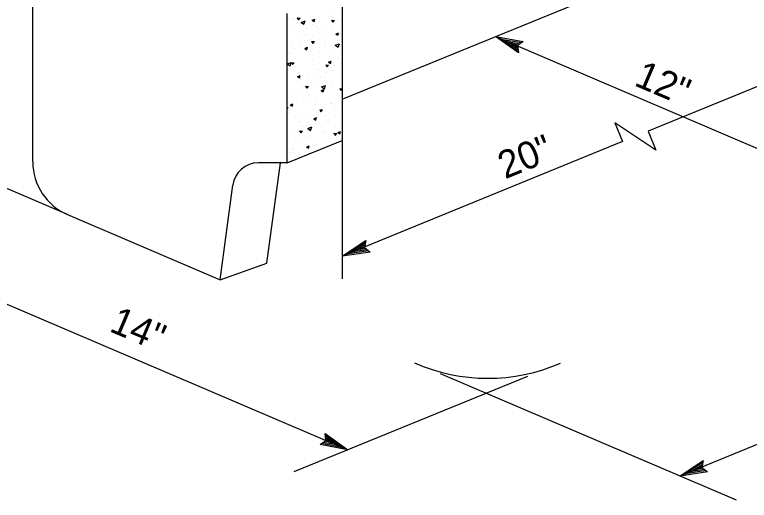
# Model space of a CAD drawing. Extents: x -121875 to -117742, y -103854 to -101122.
# Drawn here: x -120967 to -120806.9, y -101536.3 to -101430.4 of the extents above; entities that cross this region are included whole.
import ezdxf

# ---------------------------------------------------------------- set-up
doc = ezdxf.new("R2010")
doc.units = 0
for name, color, linetype in [('G-MARK', 7, 'Continuous'), ('G-TEXT', 7, 'Continuous'), ('Misc CnstDet(22)', 7, 'Continuous')]:
    doc.layers.add(name, color=color, linetype=linetype)

msp = doc.modelspace()

# ---------------------------------------------------------------- linework, layer by layer
at = {"layer": 'G-MARK'}
for p, q in [((-120862.25, -101435.17), (-120782.14, -101469.41)), ((-120955.5, -101473.99), (-120991.12, -101458.76)), ((-120670.55, -101469.09), (-120822.06, -101531.02)), ((-121000.34, -101480.05), (-120894.42, -101525.32)), ((-120855.26, -101509.32), (-120906.15, -101530.12)), ((-120809.71, -101536.3), (-120874.18, -101508.74))]:
    msp.add_line(p, q, dxfattribs=at)
msp.add_lwpolyline([(-120782.14, -101436.65), (-120828.95, -101455.78), (-120827.26, -101459.9), (-120836.23, -101453.95), (-120834.55, -101458.07), (-120895.64, -101483.05)], dxfattribs=at)
at = {"layer": 'G-TEXT'}
for p, q in [((-120857.21, -101438.69), (-120862.25, -101435.17)), ((-120862.25, -101435.17), (-120862.25, -101435.17)), ((-120862.25, -101435.17), (-120856.2, -101436.22)), ((-120857.28, -101438.28), (-120860.98, -101435.69)), ((-120860.96, -101435.69), (-120856.55, -101436.46)), ((-120857.36, -101437.86), (-120859.7, -101436.22)), ((-120859.7, -101436.22), (-120856.85, -101436.71)), ((-120856.2, -101436.22), (-120857.44, -101437.14)), ((-120856.2, -101436.22), (-120856.2, -101436.22)), ((-120857.39, -101437.47), (-120858.42, -101436.75)), ((-120858.42, -101436.75), (-120857.2, -101436.96)), ((-120857.44, -101437.14), (-120857.21, -101438.69)), ((-120857.21, -101438.69), (-120857.21, -101438.69)), ((-120895.64, -101483.05), (-120890.51, -101479.67)), ((-120894.34, -101482.55), (-120890.6, -101480.09)), ((-120893.06, -101482.06), (-120890.64, -101480.47)), ((-120891.77, -101481.57), (-120890.73, -101480.89)), ((-120890.51, -101479.67), (-120890.78, -101481.19)), ((-120890.78, -101481.19), (-120889.56, -101482.16)), ((-120890.51, -101479.67), (-120890.51, -101479.67)), ((-120889.56, -101482.16), (-120895.64, -101483.05)), ((-120889.89, -101481.91), (-120894.35, -101482.55)), ((-120890.23, -101481.65), (-120893.06, -101482.06)), ((-120890.52, -101481.39), (-120891.77, -101481.57)), ((-120889.56, -101482.16), (-120889.56, -101482.16)), ((-120895.64, -101483.05), (-120895.64, -101483.05)), ((-120899.18, -101523.24), (-120899.38, -101521.7)), ((-120899.38, -101521.7), (-120899.38, -101521.7)), ((-120899.38, -101521.7), (-120894.42, -101525.32)), ((-120899.32, -101522.11), (-120895.68, -101524.77)), ((-120899.25, -101522.53), (-120896.95, -101524.22)), ((-120900.45, -101524.14), (-120899.18, -101523.24)), ((-120894.42, -101525.32), (-120900.45, -101524.14)), ((-120900.45, -101524.14), (-120900.45, -101524.14)), ((-120895.69, -101524.77), (-120900.09, -101523.91)), ((-120896.95, -101524.22), (-120899.79, -101523.66)), ((-120898.21, -101523.66), (-120899.43, -101523.43)), ((-120899.23, -101522.92), (-120898.21, -101523.66)), ((-120894.42, -101525.32), (-120894.42, -101525.32)), ((-120822.06, -101531.02), (-120816.97, -101527.58)), ((-120816.97, -101527.58), (-120817.23, -101529.11)), ((-120816.97, -101527.58), (-120816.97, -101527.58)), ((-120820.77, -101530.51), (-120817.06, -101528)), ((-120819.49, -101530.01), (-120817.09, -101528.39)), ((-120818.21, -101529.5), (-120817.18, -101528.81)), ((-120817.23, -101529.11), (-120815.99, -101530.06)), ((-120815.99, -101530.06), (-120822.06, -101531.02)), ((-120816.32, -101529.81), (-120820.78, -101530.51)), ((-120816.67, -101529.56), (-120819.49, -101530.01)), ((-120816.96, -101529.3), (-120818.21, -101529.5)), ((-120815.99, -101530.06), (-120815.99, -101530.06)), ((-120822.06, -101531.02), (-120822.06, -101531.02))]:
    msp.add_line(p, q, dxfattribs=at)
at = {"layer": 'Misc CnstDet(22)'}
for p, q in [((-120963.09, -101462.49), (-120963.09, -101406.42)), ((-120895.64, -101448.82), (-120806.88, -101412.53)), ((-120895.64, -101424.19), (-120895.64, -101457.8)), ((-120907.62, -101462.7), (-120907.62, -101430.13)), ((-120907.12, -101431.25), (-120907.12, -101431.25)), ((-120906.29, -101431.45), (-120906.29, -101431.45)), ((-120906.25, -101431.24), (-120906.25, -101431.24)), ((-120905.42, -101431.07), (-120905.16, -101431.5)), ((-120905.42, -101431.07), (-120904.79, -101431.12)), ((-120905.16, -101431.5), (-120904.79, -101431.12)), ((-120902.19, -101431.6), (-120901.62, -101431.33)), ((-120902.19, -101431.6), (-120901.76, -101431.85)), ((-120901.76, -101431.85), (-120901.62, -101431.33)), ((-120897.94, -101431.6), (-120897.68, -101432.02)), ((-120897.94, -101431.6), (-120897.31, -101431.64)), ((-120897.85, -101430.99), (-120897.85, -101430.99)), ((-120897.62, -101430.65), (-120897.62, -101430.65)), ((-120896.76, -101431.33), (-120896.76, -101431.33)), ((-120906, -101433), (-120906, -101433)), ((-120905.48, -101432.04), (-120905.48, -101432.04)), ((-120904.61, -101432.06), (-120903.74, -101431.72)), ((-120904.61, -101432.06), (-120903.99, -101432.48)), ((-120903.99, -101432.48), (-120903.74, -101431.73)), ((-120902.21, -101432.54), (-120902.21, -101432.54)), ((-120901.22, -101433.04), (-120901.22, -101433.04)), ((-120897.68, -101432.03), (-120897.31, -101431.64)), ((-120895.94, -101432.18), (-120895.94, -101432.18)), ((-120895.84, -101431.62), (-120895.84, -101431.62)), ((-120907.51, -101433.72), (-120907.51, -101433.72)), ((-120903.16, -101433.3), (-120903.16, -101433.3)), ((-120900.73, -101433.34), (-120900.73, -101433.34)), ((-120899.22, -101433.67), (-120899.22, -101433.67)), ((-120898.02, -101433.8), (-120898.02, -101433.8)), ((-120896.99, -101434.6), (-120896.43, -101434.33)), ((-120896.99, -101434.6), (-120896.56, -101434.85)), ((-120896.56, -101434.85), (-120896.43, -101434.33)), ((-120896.18, -101434.63), (-120896.18, -101434.63)), ((-120895.97, -101434.63), (-120895.97, -101434.63)), ((-120904.6, -101435.09), (-120904.6, -101435.09)), ((-120903.47, -101435.01), (-120903.47, -101435.01)), ((-120902.59, -101435.73), (-120902.59, -101435.73)), ((-120902.33, -101436.22), (-120902.07, -101436.64)), ((-120902.33, -101436.22), (-120901.7, -101436.26)), ((-120902.07, -101436.65), (-120901.7, -101436.26)), ((-120902.04, -101435.06), (-120902.04, -101435.06)), ((-120899.29, -101436.27), (-120899.29, -101436.27)), ((-120899.21, -101435.35), (-120899.21, -101435.35)), ((-120906.46, -101436.44), (-120906.46, -101436.44)), ((-120905.97, -101437.78), (-120905.97, -101437.78)), ((-120904.74, -101437.48), (-120904.74, -101437.48)), ((-120903.79, -101437.77), (-120903.22, -101437.5)), ((-120903.79, -101437.77), (-120903.36, -101438.02)), ((-120903.36, -101438.02), (-120903.22, -101437.5)), ((-120903.14, -101437.7), (-120903.14, -101437.7)), ((-120899.56, -101436.68), (-120899.56, -101436.68)), ((-120898.09, -101437.11), (-120898.09, -101437.11)), ((-120897.14, -101437.07), (-120896.26, -101436.73)), ((-120897.14, -101437.07), (-120896.51, -101437.49)), ((-120896.51, -101437.49), (-120896.26, -101436.73)), ((-120906.86, -101438.9), (-120906.86, -101438.9)), ((-120902.93, -101438.74), (-120902.93, -101438.74)), ((-120902.5, -101438.49), (-120902.5, -101438.49)), ((-120900.55, -101438.74), (-120900.55, -101438.74)), ((-120898.38, -101439), (-120898.38, -101439)), ((-120907.62, -101441.13), (-120906.75, -101440.8)), ((-120907.62, -101441.14), (-120907, -101441.55)), ((-120907, -101441.56), (-120906.75, -101440.8)), ((-120906.72, -101440.84), (-120906.46, -101441.26)), ((-120906.72, -101440.84), (-120906.1, -101440.88)), ((-120906.46, -101441.27), (-120906.09, -101440.88)), ((-120906.31, -101440.79), (-120906.31, -101440.79)), ((-120906, -101439.95), (-120906, -101439.95)), ((-120902.1, -101440.2), (-120902.1, -101440.2)), ((-120898.59, -101440.77), (-120898.03, -101440.5)), ((-120898.59, -101440.77), (-120898.16, -101441.02)), ((-120898.55, -101440.54), (-120898.55, -101440.54)), ((-120898.16, -101441.02), (-120898.03, -101440.5)), ((-120897.87, -101440.33), (-120897.87, -101440.33)), ((-120896.42, -101440.02), (-120896.42, -101440.02)), ((-120895.86, -101440.97), (-120895.86, -101440.97)), ((-120907.27, -101442.42), (-120907.27, -101442.42)), ((-120905.77, -101441.66), (-120905.77, -101441.66)), ((-120901.81, -101441.22), (-120901.81, -101441.22)), ((-120901.25, -101442.39), (-120901.25, -101442.39)), ((-120899.24, -101441.36), (-120898.98, -101441.79)), ((-120899.24, -101441.36), (-120898.61, -101441.4)), ((-120898.98, -101441.79), (-120898.61, -101441.4)), ((-120897.69, -101442.49), (-120897.69, -101442.49)), ((-120897.35, -101441.5), (-120897.35, -101441.5)), ((-120905.39, -101443.94), (-120904.83, -101443.67)), ((-120905.39, -101443.94), (-120904.96, -101444.19)), ((-120905.21, -101442.89), (-120905.21, -101442.89)), ((-120904.96, -101444.19), (-120904.83, -101443.67)), ((-120904.66, -101443.42), (-120904.66, -101443.42)), ((-120903.08, -101443.69), (-120903.08, -101443.69)), ((-120901.82, -101443.71), (-120901.82, -101443.71)), ((-120900.45, -101444.19), (-120900.45, -101444.19)), ((-120899.24, -101443.02), (-120899.24, -101443.02)), ((-120896.2, -101443.98), (-120896.2, -101443.98)), ((-120904.62, -101444.44), (-120904.62, -101444.44)), ((-120903.63, -101445.98), (-120903.37, -101446.41)), ((-120903.63, -101445.98), (-120903.01, -101446.02)), ((-120902.62, -101445.07), (-120902.62, -101445.07)), ((-120900.7, -101445.47), (-120900.7, -101445.47)), ((-120900.15, -101446.15), (-120899.28, -101445.81)), ((-120899.53, -101446.57), (-120899.27, -101445.81)), ((-120898.95, -101444.96), (-120898.95, -101444.96)), ((-120897.87, -101445.76), (-120897.87, -101445.76)), ((-120895.69, -101445.49), (-120895.69, -101445.49)), ((-120905.99, -101447.12), (-120905.99, -101447.12)), ((-120905.11, -101446.85), (-120905.11, -101446.85)), ((-120904.34, -101446.16), (-120904.34, -101446.16)), ((-120903.37, -101446.41), (-120903, -101446.02)), ((-120900.22, -101447.44), (-120900.22, -101447.44)), ((-120900.2, -101446.94), (-120899.63, -101446.67)), ((-120900.2, -101446.94), (-120899.76, -101447.19)), ((-120900.15, -101446.15), (-120899.53, -101446.56)), ((-120899.76, -101447.19), (-120899.63, -101446.67)), ((-120899.58, -101446.03), (-120899.58, -101446.03)), ((-120896.75, -101447.52), (-120896.75, -101447.52)), ((-120896.15, -101446.5), (-120895.89, -101446.93)), ((-120896.15, -101446.5), (-120895.64, -101446.54)), ((-120895.89, -101446.93), (-120895.64, -101446.67)), ((-120905.61, -101448.63), (-120905.61, -101448.63)), ((-120902.96, -101448.08), (-120902.96, -101448.08)), ((-120902.86, -101448.55), (-120902.86, -101448.55)), ((-120901.16, -101448.9), (-120901.16, -101448.9)), ((-120896.18, -101448.73), (-120896.18, -101448.73)), ((-120907.62, -101450.63), (-120907.4, -101450.64)), ((-120907.62, -101450.88), (-120907.4, -101450.64)), ((-120906.99, -101450.11), (-120906.43, -101449.84)), ((-120906.99, -101450.11), (-120906.56, -101450.36)), ((-120906.58, -101449.75), (-120906.58, -101449.75)), ((-120906.56, -101450.36), (-120906.43, -101449.84)), ((-120906.33, -101450.13), (-120906.33, -101450.13)), ((-120901.48, -101449.91), (-120901.48, -101449.91)), ((-120898.11, -101449.85), (-120898.11, -101449.85)), ((-120897.89, -101449.68), (-120897.89, -101449.68)), ((-120895.89, -101450.31), (-120895.89, -101450.31)), ((-120907.27, -101451.78), (-120907.27, -101451.78)), ((-120906.87, -101451.1), (-120906.87, -101451.1)), ((-120904.43, -101452.07), (-120904.43, -101452.07)), ((-120902.75, -101452.38), (-120902.75, -101452.38)), ((-120901.83, -101451.05), (-120901.83, -101451.05)), ((-120901.27, -101451.73), (-120901.27, -101451.73)), ((-120900.54, -101451.12), (-120900.28, -101451.55)), ((-120900.54, -101451.12), (-120899.91, -101451.17)), ((-120900.28, -101451.55), (-120899.91, -101451.17)), ((-120899.26, -101452.36), (-120899.26, -101452.36)), ((-120897.44, -101451.2), (-120897.44, -101451.2)), ((-120897.21, -101450.95), (-120897.21, -101450.95)), ((-120897.07, -101452.35), (-120897.07, -101452.35)), ((-120904.93, -101453.74), (-120904.93, -101453.74)), ((-120904.65, -101453.78), (-120904.65, -101453.78)), ((-120903.31, -101453.83), (-120903.31, -101453.83)), ((-120901.8, -101453.11), (-120901.23, -101452.84)), ((-120901.8, -101453.11), (-120901.36, -101453.36)), ((-120901.36, -101453.36), (-120901.23, -101452.84)), ((-120898.71, -101453.67), (-120898.71, -101453.67)), ((-120896.23, -101453.32), (-120896.23, -101453.32)), ((-120904.01, -101454.85), (-120904.01, -101454.85)), ((-120903.16, -101455.22), (-120902.29, -101454.88)), ((-120903.16, -101455.22), (-120902.54, -101455.64)), ((-120902.64, -101454.41), (-120902.64, -101454.41)), ((-120902.54, -101455.64), (-120902.29, -101454.88)), ((-120900.48, -101454.12), (-120900.48, -101454.12)), ((-120900.18, -101455.04), (-120900.18, -101455.04)), ((-120899.6, -101455.37), (-120899.6, -101455.37)), ((-120906.01, -101456.47), (-120906.01, -101456.47)), ((-120904.93, -101455.74), (-120904.67, -101456.17)), ((-120904.93, -101455.74), (-120904.31, -101455.79)), ((-120904.67, -101456.17), (-120904.31, -101455.79)), ((-120899.97, -101456.15), (-120899.97, -101456.15)), ((-120899.36, -101455.88), (-120899.36, -101455.88)), ((-120897.45, -101456.26), (-120897.19, -101456.69)), ((-120897.45, -101456.26), (-120896.82, -101456.31)), ((-120897.19, -101456.7), (-120896.82, -101456.31)), ((-120896.6, -101456.11), (-120896.03, -101455.84)), ((-120896.6, -101456.11), (-120896.17, -101456.36)), ((-120896.53, -101456.17), (-120896.53, -101456.17)), ((-120896.17, -101456.36), (-120896.03, -101455.84)), ((-120907.62, -101462.7), (-120895.64, -101457.8)), ((-120907.35, -101458.1), (-120907.35, -101458.1)), ((-120905.27, -101457.32), (-120905.27, -101457.32)), ((-120903.77, -101457.26), (-120903.77, -101457.26)), ((-120902.98, -101457.42), (-120902.98, -101457.42)), ((-120901.23, -101458.62), (-120901.23, -101458.62)), ((-120895.78, -101457.41), (-120895.78, -101457.41)), ((-120895.64, -101457.8), (-120895.64, -101487.96)), ((-120906.54, -101459.79), (-120906.54, -101459.79)), ((-120906.35, -101459.48), (-120906.35, -101459.48)), ((-120903.4, -101459.28), (-120902.83, -101459.01)), ((-120903.4, -101459.28), (-120902.97, -101459.53)), ((-120902.96, -101459.53), (-120902.83, -101459.01)), ((-120902.59, -101459.4), (-120902.59, -101459.4)), ((-120899.82, -101459.31), (-120899.82, -101459.31)), ((-120907.04, -101460.44), (-120907.04, -101460.44)), ((-120906.31, -101460.6), (-120906.31, -101460.6)), ((-120907.62, -101462.7), (-120913.92, -101462.7)), ((-120912.05, -101484.57), (-120909.1, -101462.7)), ((-120922.26, -101488.2), (-120919.47, -101467.55)), ((-120955.5, -101473.99), (-120922.26, -101488.2)), ((-120922.26, -101488.2), (-120912.05, -101484.57))]:
    msp.add_line(p, q, dxfattribs=at)
for centre, radius, start, end in [((-120950.59, -101462.49), 12.5, 180, 246.8572), ((-120913.92, -101468.3), 5.6, 90, 172.321), ((-120863.89, -101470.3), 39.39, 246.0493, 293.7493)]:
    msp.add_arc(centre, radius, start, end, dxfattribs=at)

# ---------------------------------------------------------------- texts
for s, rotation, p in [('12"', 336.8572, (-120832.23, -101445.72)), ('20"', 22.2327, (-120860.13, -101466.31)), ('14"', 337.0306, (-120946.65, -101499.34))]:
    msp.add_text(s, height=6, rotation=rotation, dxfattribs=at).set_placement(p)

doc.saveas('drawing.dxf')
